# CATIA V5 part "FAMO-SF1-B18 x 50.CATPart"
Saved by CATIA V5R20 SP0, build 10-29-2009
Part number: FAMO-SF1-B18 x 50
Definition: NONE
Nomenclature: FAMO-SF1-B18 x 50
Source: Unknown
Description: FAMO-SF1-B18 x 50
Bounding box of the stored display mesh (mm): x -13 to 37, y -17 to 17, z -17 to 17
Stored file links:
  C:\Users\Utente\Desktop\IO LAVORO\3D X SITO CF\X SITO\FAMO\FAMO-SF1-B18 x 50.CATPart
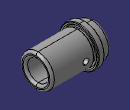
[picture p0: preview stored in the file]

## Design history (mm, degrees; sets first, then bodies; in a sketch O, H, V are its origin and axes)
Body1 "FAMO-SF1-B18 x 50" (main body)
  Solid1: solid without history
